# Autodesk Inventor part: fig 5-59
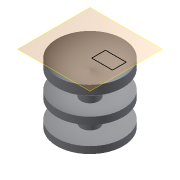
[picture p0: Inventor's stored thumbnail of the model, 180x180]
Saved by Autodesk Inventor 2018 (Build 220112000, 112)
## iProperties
Created: 2004-05
Part Number: fig 5-59
Document SubType Name: Modeling
Designer: CADCIM Technologies
Manufacturer: Standard
Standards Organization: Custom
Density: 1 g/cm^3
Material: Generic
Appearance: Default
Author: CADCIM Technologies
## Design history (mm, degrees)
sketch "Sketch1"
  geometry: L1 (0.098, 22.743)-(0.098, 0.516); L2 (-3.621, 19.305)-(-3.621, 13.061); L3 (-3.621, 10.379)-(-3.621, 3.25); L4 (-3.664, 0.516)-(0.098, 0.516); L5 (-13.694, 4.7)-(-13.694, 1.836); L6 (-13.694, 26.851)-(-13.694, 23.014); L7 (-13.694, 15.335)-(-13.694, 12.343); A1 r 10.546 centre (-4.597, 32.185) between (-13.694, 26.851) and (0.098, 22.743); A2 r 21.828 centre (-4.597, 32.185) between (-13.694, 12.343) and (-3.621, 10.379); A3 r 12.918 centre (-4.597, 32.185) between (-13.694, 23.014) and (-3.621, 19.305); A4 r 19.149 centre (-4.597, 32.185) between (-13.694, 15.335) and (-3.621, 13.061); A5 r 28.952 centre (-4.597, 32.185) between (-13.694, 4.7) and (-3.621, 3.25); A6 r 31.683 centre (-4.597, 32.185) between (-13.694, 1.836) and (-3.664, 0.516)
  constraints: 14 end point, 12 point on circle, 6 centre point, 4 perpendicular, 2 parallel, 1 vertical
revolve "Revolution1" sketch "Sketch1" stored, may be unused: angle "d0" = 90 deg
workplane "Work Plane1"
sketch "Sketch2"
  geometry: L1 (3.408, -2.846)-(12.06, -2.846); L2 (12.06, -2.846)-(12.06, 2.873); L3 (12.06, 2.873)-(3.408, 2.873); L4 (3.408, 2.873)-(3.408, -2.846)
  constraints: 8 end point, 2 parallel, 1 horizontal, 1 perpendicular
body "Solid1"
